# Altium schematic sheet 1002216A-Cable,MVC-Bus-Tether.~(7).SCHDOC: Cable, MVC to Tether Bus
size Tabloid; Organization: Monterey Bay Aquarium Research Institute; Address1: 7700 Sandholdt Rd; Address2: Moss Landing, CA 95039-9644; DocumentNumber: 1002216; Revision: A; SheetNumber: 1; SheetTotal: 1; ApprovedBy: Hans Thomas; CheckedBy: Hans Thomas; Author: Hans Thomas; CompanyName: MBARI; DrawnBy: Hans Thomas; Engineer: Hans Thomas; PageSetup: Record=PageOptions|CenterHorizontal=True|CenterVertical=True|PrintScale=0.94|XCorrection=1.00|YCorrection=1.00|PrintKind=0|BorderSize=5000000|LeftOffset=0|BottomOffset=0|Orientation=2|PaperLength=4318|PaperWidth=2794|Scale=100|PaperSource=15|PrintQuality=1200|MediaType=1|DitherType=0|PaperKind=11x17|PrintScaleMode=1
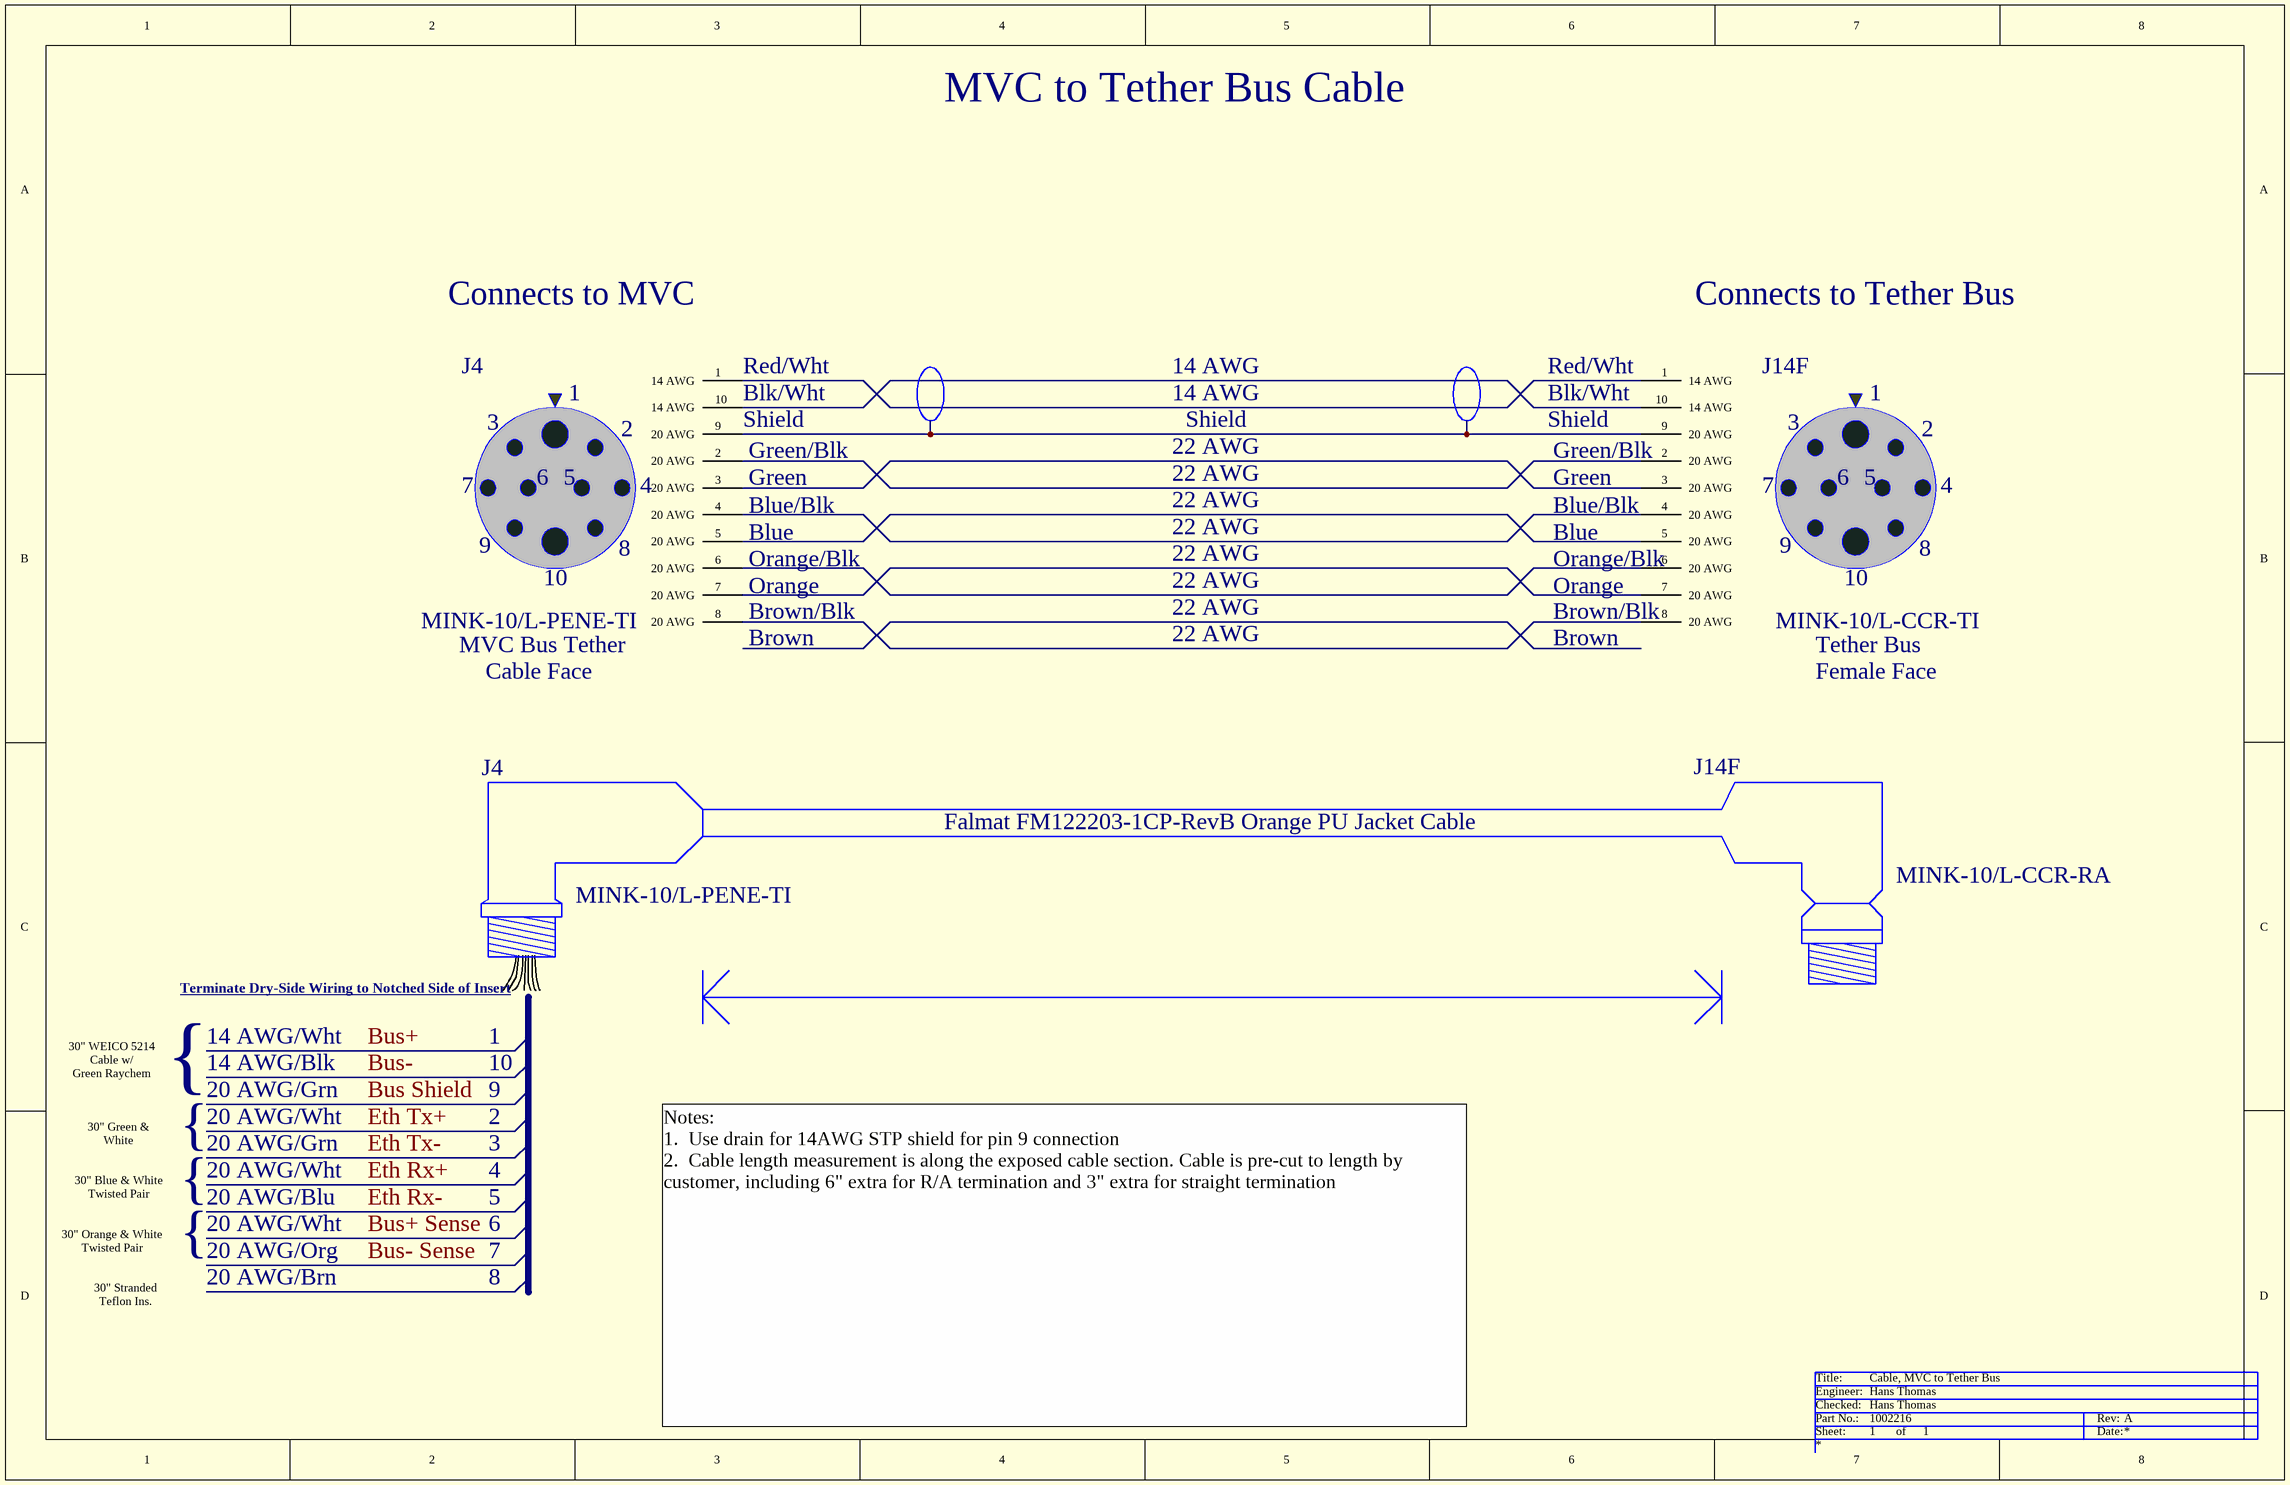
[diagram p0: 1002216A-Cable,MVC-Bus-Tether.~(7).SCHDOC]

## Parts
(Parts that share a designator on the sheet are numbered #1, #2 ... from top to bottom, then left to right.)
J4#1  MINK-10/L-PENE-TI  DescSheet: MVC Bus Tether  View: Cable Face
J4#2  MINK-10/L-PENE-TI
J14F#1  MINK-10/L-CCR-TI  DescSheet: Tether Bus  View: Female Face
J14F#2  MINK-10/L-CCR-RA

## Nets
NetJ4#1_1: J4#1.1(14_AWG) J14F#1.1(14_AWG)
NetJ4#1_2: J4#1.2(20_AWG) J14F#1.2(20_AWG)
NetJ4#1_3: J4#1.3(20_AWG) J14F#1.3(20_AWG)
NetJ4#1_4: J4#1.4(20_AWG) J14F#1.4(20_AWG)
NetJ4#1_5: J4#1.5(20_AWG) J14F#1.5(20_AWG)
NetJ4#1_6: J4#1.6(20_AWG) J14F#1.6(20_AWG)
NetJ4#1_7: J4#1.7(20_AWG) J14F#1.7(20_AWG)
NetJ4#1_8: J4#1.8(20_AWG) J14F#1.8(20_AWG)
NetJ4#1_9: J4#1.9(20_AWG) J14F#1.9(20_AWG)
NetJ4#1_10: J4#1.10(14_AWG) J14F#1.10(14_AWG)

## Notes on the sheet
- MVC to Tether Bus Cable
- Connects to MVC
- Connects to Tether Bus
- (near J4#1) Red/Wht
- (near J4#1) Blk/Wht
- (near J4#1) Shield
- 14 AWG
- Shield
- (near J14F#1) Red/Wht
- (near J14F#1) Blk/Wht
- (near J4#1) Green
- (near J4#1) Green/Blk
- 22 AWG
- Green
- (near J14F#1) Green/Blk
- (near J4#1) Blue/Blk
- (near J4#1) Blue
- (near J4#1) Orange/Blk
- (near J14F#1) Blue/Blk
- Blue
- (near J14F#1) Orange/Blk
- (near J4#1) Brown/Blk
- (near J4#1) Orange
- (near J14F#1) Brown/Blk
- Orange
- (near J4#1) Brown
- Brown
- Falmat FM122203-1CP-RevB Orange PU Jacket Cable
- Terminate Dry-Side Wiring to Notched Side of Insert
- 30" WEICO 5214 Cable w/
  Green Raychem Drain
- {
- 14 AWG/Wht
- 14 AWG/Blk
- 20 AWG/Grn
- 1
- 10
- 9
- 30" Green & White
  Twisted Pair
- 20 AWG/Wht
- 2
- 3
- 30" Blue & White
  Twisted Pair
- 20 AWG/Blu
- 4
- 5
- 6
- 30" Orange & White
  Twisted Pair
- 30" Stranded
  Teflon Ins.
- 20 AWG/Org
- 20 AWG/Brn
- 7
- 8
- Notes:
  1.  Use drain for 14AWG STP shield for pin 9 connection
  2.  Cable length measurement is along the exposed cable section. Cable is pre-cut to length by customer, including 6" extra for R/A termination and 3" extra for straight termination

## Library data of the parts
J4#1 J14F#1 = SEACON-MINK-10-BCR-PINS: Manufacturer: Seacon
J4#2 = CONN-MIN-PENE-LARGE: Seacon MIN Penetrator
J14F#2 = CONN-MIN-CCR-RA-LARGE: Seacon MIN Connector CCR Right Angle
